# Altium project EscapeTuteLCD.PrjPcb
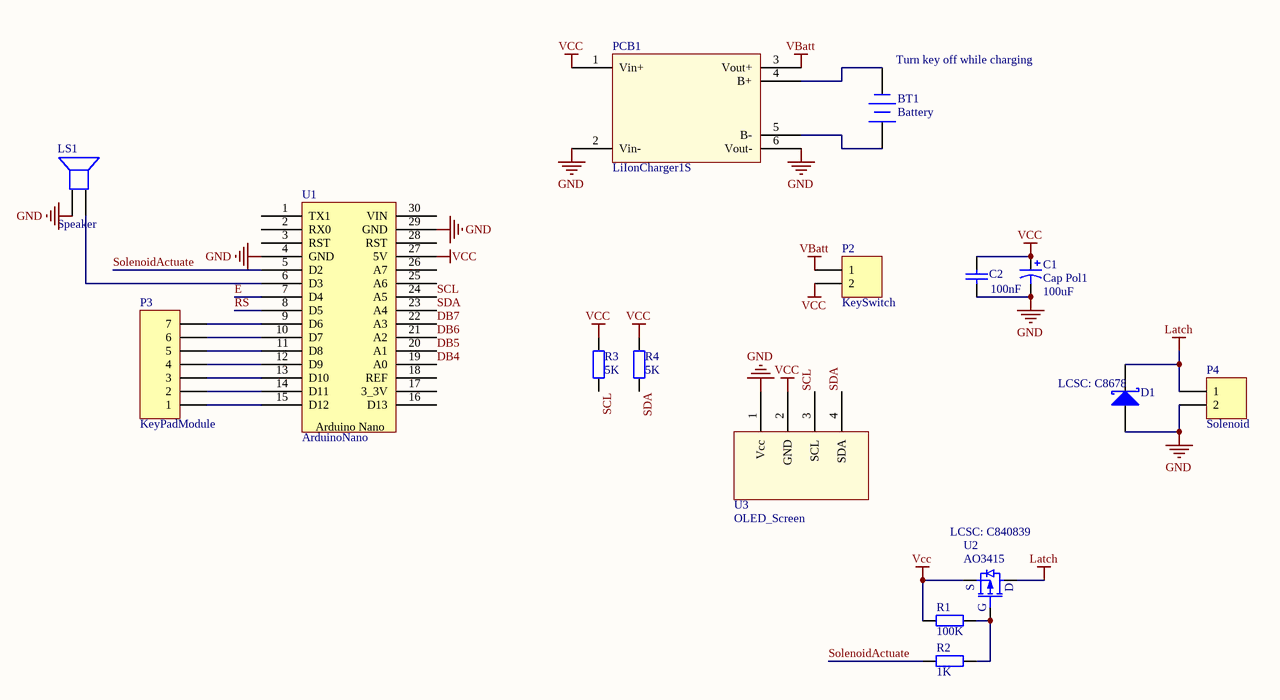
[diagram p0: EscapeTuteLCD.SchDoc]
1 sheet, 16 parts. Net scope: global (net labels, ports and power ports of the same name join across sheets).
Board file: EscapeTuteLCD.PcbDoc

## Sheet EscapeTuteLCD.SchDoc
size A4; SPICEModelCacheFMWITHVY: <root> / <DocumentId>FMWITHVY</DocumentId> / <CacheFrame Number="0"> / <Model Name="10tq035" Kind="MDL"> / <Text>*10TQ035 MCE 3/26/98 / *Ref: IR Power Semiconductors Product Digest '94 / *MCE 35V 10A 3us pkg:TO-220 3,1 / .MODEL 10TQ035 D (IS=14.2N RS=4.2M N=1.7 BV=35 IBV=15M / + CJO=412P VJ=0.75 M=0.333 TT=4.32U EG=.69 XTI=2)</Text> / </Model> / </CacheFrame> / </root>

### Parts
BT1  Battery  [Batt_18650]
C1  Cap Pol1  value 100uF  [Cap220uF]
C2  value 100nF  [6-0805_M]  (hidden comment: Cap)
D1  LCSC: C8678  [DIODE_SCHOTTKY]
LS1  Speaker  [PIEZO]
P2  KeySwitch  [KeySwitch]
P3  KeyPadModule  [HDR1X7]
P4  Solenoid  [JST_2Way_2.5mmPitch]
PCB1  LiIonCharger1S  [Charger18650]
R1  100K  [6-0805_M]
R2  1K  [6-0805_M]
R3  5K  [6-0805_M]
R4  5K  [6-0805_M]
U1  ArduinoNano  [ArduinoNano]
U2  AO3415  [SOT23_M]
U3  OLED_Screen  [OLED_Screen_2.54Inch]

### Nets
GND: C1.2 C2.1 D1.3(A) LS1.1 P4.2 PCB1.2(Vin-) PCB1.6(Vout-) U1.4(GND) U1.29(GND) U3.1(Vcc)
Latch: D1.1(K) P4.1 U2.3(D)
VBatt: P2.1 PCB1.3(Vout+)
VCC: C1.1 C2.2 P2.2 PCB1.1(Vin+) R1.1 R3.2 R4.2 U1.27(5V) U2.2(S) U3.2(GND)
DB4: U1.19(A0)
DB5: U1.20(A1)
DB6: U1.21(A2)
DB7: U1.22(A3)
E: U1.7(D4)
RS: U1.8(D5)
SCL: R3.1 U1.24(A5) U3.3(SCL)
SDA: R4.1 U1.23(A4) U3.4(SDA)
SolenoidActuate: R2.1 U1.5(D2)
NetBT1_1: BT1.1(+) PCB1.5(B-)
NetBT1_2: BT1.2(-) PCB1.4(B+)
NetLS1_2: LS1.2 U1.6(D3)
NetP3_1: P3.1 U1.15(D12)
NetP3_2: P3.2 U1.14(D11)
NetP3_3: P3.3 U1.13(D10)
NetP3_4: P3.4 U1.12(D9)
NetP3_5: P3.5 U1.11(D8)
NetP3_6: P3.6 U1.10(D7)
NetP3_7: P3.7 U1.9(D6)
NetR1_2: R1.2 R2.2 U2.1(G)

Not connected (* = marked no-connect by the designer): U1 1(TX1) 2(RX0) 3(RST) 16(D13) 17(3_3V) 18(REF) 25(A6) 26(A7) 28(RST) 30(VIN)

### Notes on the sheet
- (near BT1) Turn key off while charging
- (near U2) LCSC: C840839

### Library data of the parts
BT1 = Battery: Multicell Battery
C1 = Cap Pol1: Polarized Capacitor (Radial)
C2 = Cap: Capacitor
D1 = Diode 10TQ035: Schottky Rectifier; Note: Terminal 2 is the TAB and is electrically connected to the cathode
LS1 = Speaker: Loudspeaker
P2 P4 = Header 2: Header, 2-Pin
P3 = Header 7: Header, 7-Pin
R1 R3 R4 = RC0603FR-07100KL: RES SMD 100K OHM 1% 1/10W 0603; CompanyID: VT-00332; Solder: SMT
R2 = RC0603FR-071KL: RES SMD 1 KOHM 1% 1/10W 0603; CompanyID: VT-00574; Solder: SMT
U2 = AO3415: MOSFET P-CH 20V 4A SOT23; MFR: Alpha & Omega Semiconductor Inc.; Value: AO3015; Solder: SMT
